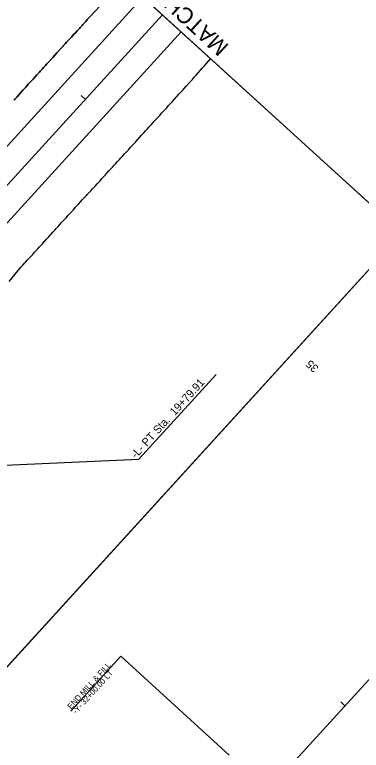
# Model space of a CAD drawing. Extents: x 1807040 to 1808827, y 913493 to 915218.
# Drawn here: x 1807918 to 1808221, y 914236 to 914879 of the extents above; entities that cross this region are included whole.
import ezdxf

# ---------------------------------------------------------------- set-up
doc = ezdxf.new("R2010")
doc.units = 0
for name, color, linetype in [('Matchline Text', 7, 'Continuous'), ('Old_Level_14', 7, 'Continuous'), ('Old_Level_18', 7, 'Continuous'), ('Prop Dimension', 7, 'Continuous'), ('Prop EOT', 7, 'Continuous'), ('Prop Horizontal Alignment Station Label', 7, 'Continuous'), ('Prop Horizontal Alignment Tick Label', 7, 'Continuous'), ('Prop Horizontal Alignment Tick Small', 7, 'Continuous'), ('Scratch_Level_0', 7, 'Continuous'), ('Scratch_Level_1', 7, 'Continuous'), ('Scratch_Level_3', 7, 'Continuous')]:
    doc.layers.add(name, color=color, linetype=linetype)

msp = doc.modelspace()

# ---------------------------------------------------------------- linework, layer by layer
at = {"layer": 'Old_Level_14'}
msp.add_line((1807868.25, 915042.04), (1808256.27, 914688.39), dxfattribs=at)
at = {"layer": 'Old_Level_18'}
msp.add_line((1808438.77, 914888.63), (1807428.35, 913780.01), dxfattribs=at)
at = {"layer": 'Prop Dimension'}
for p in [(1807966.57, 914270.43), (1808105.21, 914232.08)]:
    msp.add_line(p, (1808010.39, 914318.51), dxfattribs=at)
at = {"layer": 'Prop EOT'}
for p, q in [((1807702.96, 914536.44), (1808029.68, 914894.91)), ((1807613.95, 914371.74), (1808063.17, 914864.38))]:
    msp.add_line(p, q, dxfattribs=at)
for points in [[(1807917.03, 914804.81), (1807917.73, 914805.58), (1807919.42, 914807.42), (1807921.1, 914809.27), (1807921.42, 914809.61), (1807923.11, 914811.46), (1807924.79, 914813.3), (1807925.59, 914814.18), (1807927.26, 914816.04), (1807928.93, 914817.9), (1807929.5, 914818.54), (1807931.18, 914820.38), (1807932.87, 914822.23), (1807933.65, 914823.08), (1807935.35, 914824.92), (1807937.04, 914826.76), (1807937.58, 914827.34), (1807939.26, 914829.2), (1807939.92, 914829.93), (1807941.61, 914831.78), (1807942.84, 914833.13), (1807944.52, 914834.98), (1807945.81, 914836.4), (1807947.49, 914838.25), (1807949.17, 914840.1), (1807949.32, 914840.27), (1807950.99, 914842.13), (1807952.66, 914843.98), (1807952.89, 914844.23), (1807954.57, 914846.08), (1807956.26, 914847.93), (1807956.62, 914848.32), (1807958.31, 914850.16), (1807960.01, 914852), (1807960.08, 914852.08), (1807961.76, 914853.93), (1807963.02, 914855.31), (1807964.71, 914857.15), (1807965.48, 914858), (1807967.18, 914859.84), (1807967.96, 914860.69), (1807969.63, 914862.55), (1807970.4, 914863.39), (1807972.09, 914865.23), (1807972.46, 914865.63), (1807974.14, 914867.48), (1807974.8, 914868.2), (1807976.47, 914870.06), (1807977.22, 914870.89), (1807978.91, 914872.74), (1807979.68, 914873.59), (1807981.38, 914875.42), (1807982.17, 914876.28), (1807983.87, 914878.11), (1808013.34, 914909.8)], [(1807923.28, 914658.9), (1807924.8, 914660.56), (1807926.49, 914662.41), (1807927.21, 914663.19), (1807928.91, 914665.03), (1807930.6, 914666.86), (1807931.65, 914668), (1807933.32, 914669.86), (1807934.99, 914671.72), (1807936, 914672.83), (1807937.7, 914674.67), (1807939.4, 914676.5), (1807940.14, 914677.3), (1807941.82, 914679.14), (1807943.5, 914680.99), (1807943.89, 914681.42), (1807945.45, 914683.17), (1807947.13, 914685.01), (1807948.82, 914686.86), (1807949.24, 914687.31), (1807950.91, 914689.17), (1807952.59, 914691.02), (1807953.92, 914692.49), (1807955.61, 914694.33), (1807957.3, 914696.17), (1807958.36, 914697.32), (1807960.04, 914699.16), (1807961.73, 914701.01), (1807962.8, 914702.17), (1807964.49, 914704.01), (1807966.19, 914705.84), (1807967.25, 914706.98), (1807968.91, 914708.85), (1807970.57, 914710.71), (1807971.89, 914712.2), (1807973.58, 914714.04), (1807975.27, 914715.88), (1807976.95, 914717.7), (1807978.64, 914719.54), (1807980.33, 914721.38), (1807981.06, 914722.18), (1807982.38, 914723.54), (1807984.07, 914725.38), (1807985.75, 914727.23), (1807986.21, 914727.74), (1807987.9, 914729.58), (1807989.59, 914731.42), (1807990.58, 914732.5), (1807992.22, 914734.23), (1807993.91, 914736.08), (1807995.6, 914737.92), (1807996.63, 914739.05), (1807998.29, 914740.91), (1807999.96, 914742.78), (1808001.28, 914744.25), (1808002.98, 914746.08), (1808004.68, 914747.92), (1808005.77, 914749.09), (1808007.45, 914750.95), (1808009.13, 914752.8), (1808010.48, 914754.29), (1808012.18, 914756.13), (1808013.88, 914757.96), (1808015.62, 914759.83), (1808017.29, 914761.69), (1808018.96, 914763.55), (1808019.98, 914764.69), (1808021.68, 914766.52), (1808023.38, 914768.36), (1808025.08, 914770.19), (1808025.16, 914770.28), (1808026.83, 914772.15), (1808028.49, 914774.01), (1808030.16, 914775.88), (1808030.35, 914776.09), (1808032.05, 914777.93), (1808033.74, 914779.77), (1808035.17, 914781.31), (1808036.84, 914783.17), (1808038.52, 914785.03), (1808039.57, 914786.19), (1808041.27, 914788.02), (1808042.96, 914789.86), (1808044.37, 914791.37), (1808046.06, 914793.21), (1808047.75, 914795.06), (1808048.81, 914796.21), (1808050.47, 914798.08), (1808052.14, 914799.94), (1808053.78, 914801.78), (1808055.47, 914803.62), (1808057.16, 914805.47), (1808058.84, 914807.31), (1808059.46, 914807.99), (1808061.15, 914809.84), (1808062.84, 914811.68), (1808064.2, 914813.17), (1808065.88, 914815.02), (1808067.55, 914816.88), (1808069.23, 914818.73), (1808069.59, 914819.13), (1808071.26, 914820.99), (1808072.92, 914822.86), (1808074.58, 914824.73), (1808074.87, 914825.05), (1808076.52, 914826.93), (1808078.16, 914828.8), (1808079.81, 914830.68), (1808080.08, 914830.99), (1808081.74, 914832.86), (1808083.4, 914834.73), (1808085.05, 914836.6), (1808085.3, 914836.88), (1808086.94, 914838.77), (1808088.85, 914840.97)], [(1807912.79, 914646.15), (1807923.28, 914658.9)]]:
    msp.add_lwpolyline(points, dxfattribs=at)
at = {"layer": 'Prop Horizontal Alignment Station Label'}
for p, q in [((1808026.15, 914490.91), (1808093.62, 914564.93)), ((1807899.5, 914485.04), (1808026.15, 914490.91))]:
    msp.add_line(p, q, dxfattribs=at)
at = {"layer": 'Prop Horizontal Alignment Tick Small'}
for p, q in [((1807979.31, 914805.51), (1807975.62, 914808.87)), ((1808206.34, 914275.21), (1808202.64, 914278.58))]:
    msp.add_line(p, q, dxfattribs=at)
at = {"layer": 'Scratch_Level_0'}
for p, q in [((1807702.96, 914536.44), (1808029.68, 914894.91)), ((1808063.17, 914864.38), (1807658.9, 914421.03)), ((1808088.85, 914840.97), (1808063.17, 914864.38))]:
    msp.add_line(p, q, dxfattribs=at)
for points in [[(1808013.34, 914909.8), (1807983.87, 914878.11), (1807982.17, 914876.28), (1807981.38, 914875.42), (1807979.68, 914873.59), (1807978.91, 914872.74), (1807977.22, 914870.89), (1807976.47, 914870.06), (1807974.8, 914868.2), (1807974.14, 914867.48), (1807972.46, 914865.63), (1807972.09, 914865.23), (1807970.4, 914863.39), (1807969.63, 914862.55), (1807967.96, 914860.69), (1807967.18, 914859.84), (1807965.48, 914858), (1807964.71, 914857.15), (1807963.02, 914855.31), (1807961.76, 914853.93), (1807960.08, 914852.08), (1807960.01, 914852), (1807958.31, 914850.16), (1807956.62, 914848.32), (1807956.26, 914847.93), (1807954.57, 914846.08), (1807952.89, 914844.23), (1807952.66, 914843.98), (1807950.99, 914842.13), (1807949.32, 914840.27), (1807949.17, 914840.1), (1807947.49, 914838.25), (1807945.81, 914836.4), (1807944.52, 914834.98), (1807942.84, 914833.13), (1807941.61, 914831.78), (1807939.92, 914829.93), (1807939.26, 914829.2), (1807937.58, 914827.34), (1807937.04, 914826.76), (1807935.35, 914824.92), (1807933.65, 914823.08), (1807932.87, 914822.23), (1807931.18, 914820.38), (1807929.5, 914818.54), (1807928.93, 914817.9), (1807927.26, 914816.04), (1807925.59, 914814.18), (1807924.79, 914813.3), (1807923.11, 914811.46), (1807921.42, 914809.61), (1807921.1, 914809.27), (1807919.42, 914807.42), (1807917.73, 914805.58), (1807917.03, 914804.81)], [(1807923.28, 914658.9), (1807924.8, 914660.56), (1807926.49, 914662.41), (1807927.21, 914663.19), (1807928.91, 914665.03), (1807930.6, 914666.86), (1807931.65, 914668), (1807933.32, 914669.86), (1807934.99, 914671.72), (1807936, 914672.83), (1807937.7, 914674.67), (1807939.4, 914676.5), (1807940.14, 914677.3), (1807941.82, 914679.14), (1807943.5, 914680.99), (1807943.89, 914681.42), (1807945.45, 914683.17), (1807947.13, 914685.01), (1807948.82, 914686.86), (1807949.24, 914687.31), (1807950.91, 914689.17), (1807952.59, 914691.02), (1807953.92, 914692.49), (1807955.61, 914694.33), (1807957.3, 914696.17), (1807958.36, 914697.32), (1807960.04, 914699.16), (1807961.73, 914701.01), (1807962.8, 914702.17), (1807964.49, 914704.01), (1807966.19, 914705.84), (1807967.25, 914706.98), (1807968.91, 914708.85), (1807970.57, 914710.71), (1807971.89, 914712.2), (1807973.58, 914714.04), (1807975.27, 914715.88), (1807976.95, 914717.7), (1807978.64, 914719.54), (1807980.33, 914721.38), (1807981.06, 914722.18), (1807982.38, 914723.54), (1807984.07, 914725.38), (1807985.75, 914727.23), (1807986.21, 914727.74), (1807987.9, 914729.58), (1807989.59, 914731.42), (1807990.58, 914732.5), (1807992.22, 914734.23), (1807993.91, 914736.08), (1807995.6, 914737.92), (1807996.63, 914739.05), (1807998.29, 914740.91), (1807999.96, 914742.78), (1808001.28, 914744.25), (1808002.98, 914746.08), (1808004.68, 914747.92), (1808005.77, 914749.09), (1808007.45, 914750.95), (1808009.13, 914752.8), (1808010.48, 914754.29), (1808012.18, 914756.13), (1808013.88, 914757.96), (1808015.62, 914759.83), (1808017.29, 914761.69), (1808018.96, 914763.55), (1808019.98, 914764.69), (1808021.68, 914766.52), (1808023.38, 914768.36), (1808025.08, 914770.19), (1808025.16, 914770.28), (1808026.83, 914772.15), (1808028.49, 914774.01), (1808030.16, 914775.88), (1808030.35, 914776.09), (1808032.05, 914777.93), (1808033.74, 914779.77), (1808035.17, 914781.31), (1808036.84, 914783.17), (1808038.52, 914785.03), (1808039.57, 914786.19), (1808041.27, 914788.02), (1808042.96, 914789.86), (1808044.37, 914791.37), (1808046.06, 914793.21), (1808047.75, 914795.06), (1808048.81, 914796.21), (1808050.47, 914798.08), (1808052.14, 914799.94), (1808053.78, 914801.78), (1808055.47, 914803.62), (1808057.16, 914805.47), (1808058.84, 914807.31), (1808059.46, 914807.99), (1808061.15, 914809.84), (1808062.84, 914811.68), (1808064.2, 914813.17), (1808065.88, 914815.02), (1808067.55, 914816.88), (1808069.23, 914818.73), (1808069.59, 914819.13), (1808071.26, 914820.99), (1808072.92, 914822.86), (1808074.58, 914824.73), (1808074.87, 914825.05), (1808076.52, 914826.93), (1808078.16, 914828.8), (1808079.81, 914830.68), (1808080.08, 914830.99), (1808081.74, 914832.86), (1808083.4, 914834.73), (1808085.05, 914836.6), (1808085.3, 914836.88), (1808086.94, 914838.77), (1808088.85, 914840.97)], [(1807912.79, 914646.15), (1807923.28, 914658.9)]]:
    msp.add_lwpolyline(points, dxfattribs=at)
at = {"layer": 'Scratch_Level_1'}
for points in [[(1807040.33, 914133.66), (1807040.33, 914133.66), (1807428.35, 913780.01), (1808256.27, 914688.39), (1807868.25, 915042.04)], [(1807489.01, 913846.57), (1807877.03, 913492.93), (1808826.79, 914534.98), (1808438.77, 914888.63)]]:
    msp.add_lwpolyline(points, close=True, dxfattribs=at)
at = {"layer": 'Scratch_Level_3'}
for p, q in [((1807238.34, 913992.52), (1808046.68, 914879.41)), ((1807667.44, 913683.95), (1808610.51, 914718.66))]:
    msp.add_line(p, q, dxfattribs=at)

# ---------------------------------------------------------------- texts
at = {"layer": 'Matchline Text'}
msp.add_text('MATCHLINE A', height=14, rotation=137.47907, dxfattribs=at).set_placement((1808105.58, 914852.44))
at = {"layer": 'Prop Dimension'}
for s, p in [('END MILL & FILL', (1807966.88, 914271.74)), ('-Y- 32+00.00 LT', (1807971.31, 914267.7))]:
    msp.add_text(s, height=5, rotation=47.65322, dxfattribs=at).set_placement(p)
at = {"layer": 'Prop Horizontal Alignment Station Label'}
msp.add_text('-L- PT Sta.  19+79.91', height=7, rotation=47.64597, dxfattribs=at).set_placement((1808023.6, 914491.05))
at = {"layer": 'Prop Horizontal Alignment Tick Label'}
msp.add_text('35', height=7, rotation=137.65322, dxfattribs=at).set_placement((1808183.84, 914571.06))

doc.saveas('drawing.dxf')
